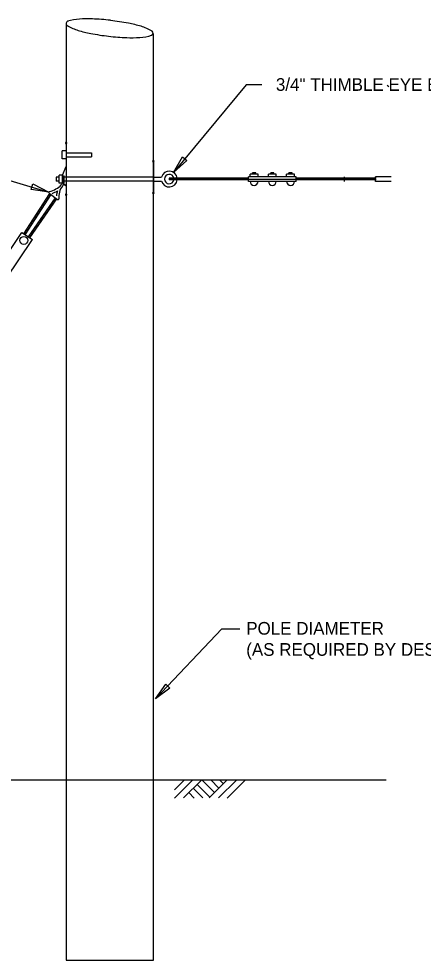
# Model space of a CAD drawing. Extents: x 1299104.8 to 1299141.6, y 239639.8 to 239661.8.
# Drawn here: x 1299120.32 to 1299124.15, y 239645.41 to 239654.32 of the extents above; entities that cross this region are included whole.
import ezdxf

# ---------------------------------------------------------------- set-up
doc = ezdxf.new("R2010")
doc.units = 0
doc.layers.add('DIM TXT', color=7, linetype='Continuous')

msp = doc.modelspace()

# ---------------------------------------------------------------- linework, layer by layer
at = {"layer": 'DIM TXT'}
for p, q in [((1299120.77, 239654.2729), (1299120.77, 239647.1125)), ((1299121.595, 239647.1125), (1299121.595, 239654.1755)), ((1299122.4738, 239653.6946), (1299121.786, 239652.8652)), ((1299122.6208, 239653.6946), (1299122.4738, 239653.6946)), ((1299123.8057, 239653.6923), (1299123.8207, 239653.6773)), ((1299120.7625, 239653.0683), (1299120.7325, 239653.0683)), ((1299120.7325, 239652.9933), (1299120.7325, 239653.0683)), ((1299120.77, 239653.0495), (1299121.01, 239653.0495)), ((1299121.01, 239653.0495), (1299121.01, 239653.012)), ((1299119.5594, 239652.9893), (1299120.6069, 239652.68)), ((1299120.7625, 239652.9933), (1299120.7325, 239652.9933)), ((1299120.77, 239653.012), (1299121.01, 239653.012)), ((1299120.7344, 239652.8386), (1299120.77, 239652.9214)), ((1299122.5325, 239652.8474), (1299122.5325, 239652.8624)), ((1299122.5625, 239652.8624), (1299122.5325, 239652.8624)), ((1299122.5625, 239652.8474), (1299122.5625, 239652.8624)), ((1299122.705, 239652.8474), (1299122.705, 239652.8624)), ((1299122.735, 239652.8624), (1299122.705, 239652.8624)), ((1299122.735, 239652.8474), (1299122.735, 239652.8624)), ((1299122.8775, 239652.8474), (1299122.8775, 239652.8624)), ((1299122.9075, 239652.8624), (1299122.8775, 239652.8624)), ((1299122.9075, 239652.8474), (1299122.9075, 239652.8624)), ((1299120.6771, 239652.8211), (1299120.6771, 239652.7836)), ((1299120.7044, 239652.8211), (1299120.6771, 239652.8211)), ((1299120.7044, 239652.7836), (1299120.6771, 239652.7836)), ((1299120.7044, 239652.7636), (1299120.7044, 239652.8386)), ((1299120.7344, 239652.8386), (1299120.7044, 239652.8386)), ((1299120.7344, 239652.7636), (1299120.7044, 239652.7636)), ((1299120.7344, 239652.7636), (1299120.7344, 239652.8386)), ((1299121.595, 239652.8211), (1299120.7344, 239652.8211)), ((1299121.595, 239652.7836), (1299120.7344, 239652.7836)), ((1299120.7387, 239652.7821), (1299120.7387, 239652.8326)), ((1299120.7387, 239652.8326), (1299120.7524, 239652.8326)), ((1299120.7524, 239652.7813), (1299120.7524, 239652.8326)), ((1299121.595, 239652.8211), (1299121.6724, 239652.8211)), ((1299121.595, 239652.7836), (1299121.6724, 239652.7836)), ((1299122.495, 239652.8099), (1299121.745, 239652.8099)), ((1299121.745, 239652.8099), (1299121.745, 239652.7949)), ((1299121.745, 239652.8099), (1299121.76, 239652.7949)), ((1299122.495, 239652.7949), (1299121.745, 239652.7949)), ((1299121.76, 239652.8099), (1299121.775, 239652.7949)), ((1299121.775, 239652.8099), (1299121.79, 239652.7949)), ((1299121.79, 239652.8099), (1299121.805, 239652.7949)), ((1299121.805, 239652.8099), (1299121.82, 239652.7949)), ((1299121.82, 239652.8099), (1299121.835, 239652.7949)), ((1299121.835, 239652.8099), (1299121.85, 239652.7949)), ((1299121.85, 239652.8099), (1299121.865, 239652.7949)), ((1299121.865, 239652.8099), (1299121.88, 239652.7949)), ((1299121.88, 239652.8099), (1299121.895, 239652.7949)), ((1299121.895, 239652.8099), (1299121.91, 239652.7949)), ((1299121.91, 239652.8099), (1299121.925, 239652.7949)), ((1299121.925, 239652.8099), (1299121.94, 239652.7949)), ((1299121.94, 239652.8099), (1299121.955, 239652.7949)), ((1299121.955, 239652.8099), (1299121.97, 239652.7949)), ((1299121.97, 239652.8099), (1299121.985, 239652.7949)), ((1299121.985, 239652.8099), (1299122, 239652.7949)), ((1299122, 239652.8099), (1299122.015, 239652.7949)), ((1299122.015, 239652.8099), (1299122.03, 239652.7949)), ((1299122.03, 239652.8099), (1299122.045, 239652.7949)), ((1299122.045, 239652.8099), (1299122.06, 239652.7949)), ((1299122.06, 239652.8099), (1299122.075, 239652.7949)), ((1299122.075, 239652.8099), (1299122.09, 239652.7949)), ((1299122.09, 239652.8099), (1299122.105, 239652.7949)), ((1299122.105, 239652.8099), (1299122.12, 239652.7949)), ((1299122.12, 239652.8099), (1299122.135, 239652.7949)), ((1299122.135, 239652.8099), (1299122.15, 239652.7949)), ((1299122.15, 239652.8099), (1299122.165, 239652.7949)), ((1299122.165, 239652.8099), (1299122.18, 239652.7949)), ((1299122.18, 239652.8099), (1299122.195, 239652.7949)), ((1299122.195, 239652.8099), (1299122.21, 239652.7949)), ((1299122.21, 239652.8099), (1299122.225, 239652.7949)), ((1299122.225, 239652.8099), (1299122.24, 239652.7949)), ((1299122.24, 239652.8099), (1299122.255, 239652.7949)), ((1299122.255, 239652.8099), (1299122.27, 239652.7949)), ((1299122.27, 239652.8099), (1299122.285, 239652.7949)), ((1299122.285, 239652.8099), (1299122.3, 239652.7949)), ((1299122.3, 239652.8099), (1299122.315, 239652.7949)), ((1299122.315, 239652.8099), (1299122.33, 239652.7949)), ((1299122.33, 239652.8099), (1299122.345, 239652.7949)), ((1299122.345, 239652.8099), (1299122.36, 239652.7949)), ((1299122.36, 239652.8099), (1299122.375, 239652.7949)), ((1299122.375, 239652.8099), (1299122.39, 239652.7949)), ((1299122.39, 239652.8099), (1299122.405, 239652.7949)), ((1299122.405, 239652.8099), (1299122.42, 239652.7949)), ((1299122.42, 239652.8099), (1299122.435, 239652.7949)), ((1299122.435, 239652.8099), (1299122.45, 239652.7949)), ((1299122.45, 239652.8099), (1299122.465, 239652.7949)), ((1299122.465, 239652.8099), (1299122.48, 239652.7949)), ((1299122.48, 239652.8099), (1299122.495, 239652.7949)), ((1299122.495, 239652.7799), (1299122.495, 239652.8249)), ((1299122.945, 239652.8249), (1299122.495, 239652.8249)), ((1299122.495, 239652.8024), (1299122.945, 239652.8024)), ((1299122.945, 239652.7799), (1299122.495, 239652.7799)), ((1299122.51, 239652.8249), (1299122.51, 239652.8474)), ((1299122.585, 239652.8474), (1299122.51, 239652.8474)), ((1299122.585, 239652.8249), (1299122.585, 239652.8474)), ((1299122.7575, 239652.8474), (1299122.6825, 239652.8474)), ((1299122.6825, 239652.8249), (1299122.6825, 239652.8474)), ((1299122.7575, 239652.8249), (1299122.7575, 239652.8474)), ((1299122.855, 239652.8249), (1299122.855, 239652.8474)), ((1299122.93, 239652.8474), (1299122.855, 239652.8474)), ((1299122.93, 239652.8249), (1299122.93, 239652.8474)), ((1299122.945, 239652.7799), (1299122.945, 239652.8249)), ((1299123.695, 239652.8099), (1299122.945, 239652.8099)), ((1299122.945, 239652.8099), (1299122.96, 239652.7949)), ((1299123.695, 239652.7949), (1299122.945, 239652.7949)), ((1299122.96, 239652.8099), (1299122.975, 239652.7949)), ((1299122.975, 239652.8099), (1299122.99, 239652.7949)), ((1299122.99, 239652.8099), (1299123.005, 239652.7949)), ((1299123.005, 239652.8099), (1299123.02, 239652.7949)), ((1299123.02, 239652.8099), (1299123.035, 239652.7949)), ((1299123.035, 239652.8099), (1299123.05, 239652.7949)), ((1299123.05, 239652.8099), (1299123.065, 239652.7949)), ((1299123.065, 239652.8099), (1299123.08, 239652.7949)), ((1299123.08, 239652.8099), (1299123.095, 239652.7949)), ((1299123.095, 239652.8099), (1299123.11, 239652.7949)), ((1299123.11, 239652.8099), (1299123.125, 239652.7949)), ((1299123.125, 239652.8099), (1299123.14, 239652.7949)), ((1299123.14, 239652.8099), (1299123.155, 239652.7949)), ((1299123.155, 239652.8099), (1299123.17, 239652.7949)), ((1299123.17, 239652.8099), (1299123.185, 239652.7949)), ((1299123.185, 239652.8099), (1299123.2, 239652.7949)), ((1299123.2, 239652.8099), (1299123.215, 239652.7949)), ((1299123.215, 239652.8099), (1299123.23, 239652.7949)), ((1299123.23, 239652.8099), (1299123.245, 239652.7949)), ((1299123.245, 239652.8099), (1299123.26, 239652.7949)), ((1299123.26, 239652.8099), (1299123.275, 239652.7949)), ((1299123.275, 239652.8099), (1299123.29, 239652.7949)), ((1299123.29, 239652.8099), (1299123.305, 239652.7949)), ((1299123.305, 239652.8099), (1299123.32, 239652.7949)), ((1299123.32, 239652.8099), (1299123.335, 239652.7949)), ((1299123.335, 239652.8099), (1299123.35, 239652.7949)), ((1299123.35, 239652.8099), (1299123.365, 239652.7949)), ((1299123.365, 239652.8099), (1299123.38, 239652.7949)), ((1299123.38, 239652.8099), (1299123.395, 239652.7949)), ((1299123.395, 239652.8099), (1299123.41, 239652.7949)), ((1299123.4036, 239652.7799), (1299123.4036, 239652.8249)), ((1299123.7036, 239652.8099), (1299123.4036, 239652.8099)), ((1299123.4036, 239652.8099), (1299123.4186, 239652.7949)), ((1299123.7036, 239652.7949), (1299123.4036, 239652.7949)), ((1299123.41, 239652.8099), (1299123.425, 239652.7949)), ((1299123.4186, 239652.8099), (1299123.4336, 239652.7949)), ((1299123.425, 239652.8099), (1299123.44, 239652.7949)), ((1299123.4336, 239652.8099), (1299123.4486, 239652.7949)), ((1299123.44, 239652.8099), (1299123.455, 239652.7949)), ((1299123.4486, 239652.8099), (1299123.4636, 239652.7949)), ((1299123.455, 239652.8099), (1299123.47, 239652.7949)), ((1299123.4636, 239652.8099), (1299123.4786, 239652.7949)), ((1299123.47, 239652.8099), (1299123.485, 239652.7949)), ((1299123.4786, 239652.8099), (1299123.4936, 239652.7949)), ((1299123.485, 239652.8099), (1299123.5, 239652.7949)), ((1299123.4936, 239652.8099), (1299123.5086, 239652.7949)), ((1299123.5, 239652.8099), (1299123.515, 239652.7949)), ((1299123.5086, 239652.8099), (1299123.5236, 239652.7949)), ((1299123.515, 239652.8099), (1299123.53, 239652.7949)), ((1299123.5236, 239652.8099), (1299123.5386, 239652.7949)), ((1299123.53, 239652.8099), (1299123.545, 239652.7949)), ((1299123.5386, 239652.8099), (1299123.5536, 239652.7949)), ((1299123.545, 239652.8099), (1299123.56, 239652.7949)), ((1299123.5536, 239652.8099), (1299123.5686, 239652.7949)), ((1299123.56, 239652.8099), (1299123.575, 239652.7949)), ((1299123.5686, 239652.8099), (1299123.5836, 239652.7949)), ((1299123.575, 239652.8099), (1299123.59, 239652.7949)), ((1299123.5836, 239652.8099), (1299123.5986, 239652.7949)), ((1299123.59, 239652.8099), (1299123.605, 239652.7949)), ((1299123.5986, 239652.8099), (1299123.6136, 239652.7949)), ((1299123.605, 239652.8099), (1299123.62, 239652.7949)), ((1299123.6136, 239652.8099), (1299123.6286, 239652.7949)), ((1299123.62, 239652.8099), (1299123.635, 239652.7949)), ((1299123.6286, 239652.8099), (1299123.6436, 239652.7949)), ((1299123.635, 239652.8099), (1299123.65, 239652.7949)), ((1299123.6436, 239652.8099), (1299123.6586, 239652.7949)), ((1299123.65, 239652.8099), (1299123.665, 239652.7949)), ((1299123.665, 239652.8099), (1299123.68, 239652.7949)), ((1299123.68, 239652.8099), (1299123.695, 239652.7949)), ((1299123.695, 239652.7799), (1299123.695, 239652.8249)), ((1299123.845, 239652.8249), (1299123.695, 239652.8249)), ((1299123.845, 239652.7799), (1299123.695, 239652.7799)), ((1299120.7471, 239652.7547), (1299120.77, 239652.7386)), ((1299120.3702, 239652.2839), (1299120.6164, 239652.6649)), ((1299120.3826, 239652.2756), (1299120.6283, 239652.6558)), ((1299120.413, 239652.2552), (1299120.6701, 239652.6242)), ((1299120.4254, 239652.2468), (1299120.6819, 239652.6149)), ((1299120.5866, 239652.5913), (1299120.5659, 239652.5868)), ((1299120.5948, 239652.6039), (1299120.574, 239652.5994)), ((1299120.6029, 239652.6165), (1299120.5822, 239652.612)), ((1299120.6111, 239652.6291), (1299120.5903, 239652.6246)), ((1299120.6192, 239652.6417), (1299120.5985, 239652.6372)), ((1299120.6273, 239652.6543), (1299120.6066, 239652.6498)), ((1299120.609, 239652.6705), (1299120.6891, 239652.6095)), ((1299120.6632, 239652.5881), (1299120.6424, 239652.5844)), ((1299120.6718, 239652.6004), (1299120.6509, 239652.5967)), ((1299120.6804, 239652.6127), (1299120.6595, 239652.609)), ((1299120.5296, 239652.5031), (1299120.5089, 239652.4986)), ((1299120.5378, 239652.5157), (1299120.5171, 239652.5112)), ((1299120.5459, 239652.5283), (1299120.5252, 239652.5238)), ((1299120.5541, 239652.5409), (1299120.5333, 239652.5364)), ((1299120.5622, 239652.5535), (1299120.5415, 239652.549)), ((1299120.5704, 239652.5661), (1299120.5496, 239652.5616)), ((1299120.5785, 239652.5787), (1299120.5578, 239652.5742)), ((1299120.6032, 239652.502), (1299120.5823, 239652.4982)), ((1299120.6118, 239652.5143), (1299120.5909, 239652.5105)), ((1299120.6204, 239652.5266), (1299120.5995, 239652.5228)), ((1299120.6289, 239652.5389), (1299120.608, 239652.5352)), ((1299120.6375, 239652.5512), (1299120.6166, 239652.5475)), ((1299120.6461, 239652.5635), (1299120.6252, 239652.5598)), ((1299120.6547, 239652.5758), (1299120.6338, 239652.5721)), ((1299120.4727, 239652.4149), (1299120.4519, 239652.4104)), ((1299120.4808, 239652.4275), (1299120.4601, 239652.423)), ((1299120.4889, 239652.4401), (1299120.4682, 239652.4356)), ((1299120.4971, 239652.4527), (1299120.4763, 239652.4482)), ((1299120.5052, 239652.4653), (1299120.4845, 239652.4608)), ((1299120.5134, 239652.4779), (1299120.4926, 239652.4734)), ((1299120.5215, 239652.4905), (1299120.5008, 239652.486)), ((1299120.5346, 239652.4035), (1299120.5137, 239652.3998)), ((1299120.5432, 239652.4158), (1299120.5223, 239652.4121)), ((1299120.5517, 239652.4281), (1299120.5309, 239652.4244)), ((1299120.5603, 239652.4404), (1299120.5394, 239652.4367)), ((1299120.5689, 239652.4527), (1299120.548, 239652.449)), ((1299120.5775, 239652.465), (1299120.5566, 239652.4613)), ((1299120.586, 239652.4773), (1299120.5652, 239652.4736)), ((1299120.5946, 239652.4897), (1299120.5737, 239652.4859)), ((1299120.4157, 239652.3267), (1299120.3949, 239652.3222)), ((1299120.4238, 239652.3393), (1299120.4031, 239652.3348)), ((1299120.432, 239652.3519), (1299120.4112, 239652.3474)), ((1299120.4401, 239652.3645), (1299120.4194, 239652.36)), ((1299120.4482, 239652.3771), (1299120.4275, 239652.3726)), ((1299120.4564, 239652.3897), (1299120.4356, 239652.3852)), ((1299120.4645, 239652.4023), (1299120.4438, 239652.3978)), ((1299120.4746, 239652.3174), (1299120.4537, 239652.3136)), ((1299120.4831, 239652.3297), (1299120.4623, 239652.3259)), ((1299120.4917, 239652.342), (1299120.4708, 239652.3382)), ((1299120.5003, 239652.3543), (1299120.4794, 239652.3506)), ((1299120.5089, 239652.3666), (1299120.488, 239652.3629)), ((1299120.5174, 239652.3789), (1299120.4966, 239652.3752)), ((1299120.526, 239652.3912), (1299120.5051, 239652.3875)), ((1299120.1004, 239651.923), (1299120.3512, 239652.2966)), ((1299120.2001, 239651.8561), (1299120.4509, 239652.2298)), ((1299120.3512, 239652.2966), (1299120.4509, 239652.2298)), ((1299120.3912, 239652.2889), (1299120.3705, 239652.2844)), ((1299120.3994, 239652.3015), (1299120.3786, 239652.297)), ((1299120.3831, 239652.2763), (1299120.3821, 239652.2761)), ((1299120.4075, 239652.3141), (1299120.3868, 239652.3096)), ((1299120.4317, 239652.2558), (1299120.4164, 239652.2531)), ((1299120.4403, 239652.2681), (1299120.4194, 239652.2644)), ((1299120.4488, 239652.2804), (1299120.428, 239652.2767)), ((1299120.4574, 239652.2928), (1299120.4365, 239652.289)), ((1299120.466, 239652.3051), (1299120.4451, 239652.3013)), ((1299122.2433, 239648.5466), (1299121.614, 239647.8852)), ((1299122.2433, 239648.5466), (1299122.4137, 239648.5466)), ((1299114.989, 239647.1184), (1299123.7976, 239647.1184)), ((1299120.77, 239647.1125), (1299120.77, 239645.4117)), ((1299121.595, 239645.4117), (1299121.595, 239647.1125)), ((1299121.7938, 239647.0246), (1299121.8882, 239647.1183)), ((1299121.7938, 239646.9441), (1299121.9693, 239647.1183)), ((1299121.8813, 239646.9477), (1299122.0531, 239647.1183)), ((1299122.0098, 239647.0754), (1299122.1291, 239646.9551)), ((1299122.054, 239647.1183), (1299122.1738, 239646.9977)), ((1299122.1216, 239646.9468), (1299122.2944, 239647.1183)), ((1299122.1372, 239647.1183), (1299122.2147, 239647.0402)), ((1299122.2098, 239646.9464), (1299122.383, 239647.1183)), ((1299122.2214, 239647.1183), (1299122.2576, 239647.0818)), ((1299122.2933, 239646.9461), (1299122.4668, 239647.1183)), ((1299121.9307, 239646.9967), (1299121.9823, 239646.9445)), ((1299121.9725, 239647.0383), (1299122.0631, 239646.947)), ((1299120.77, 239645.4117), (1299121.595, 239645.4117))]:
    msp.add_line(p, q, dxfattribs=at)
for points in [[(1299120.77, 239653.1433), (1299120.77, 239652.6558)], [(1299121.595, 239652.9711), (1299121.595, 239652.6711)], [(1299120.7344, 239652.8386), (1299120.77, 239652.9214)], [(1299120.7471, 239652.7547), (1299120.7471, 239652.7547), (1299120.7471, 239652.7547), (1299120.7471, 239652.7547), (1299120.7471, 239652.7547)], [(1299120.77, 239652.7386), (1299120.7471, 239652.7547)]]:
    msp.add_lwpolyline(points, dxfattribs=at)
for points in [[(1299121.8694, 239653.0122), (1299121.9118, 239652.9781), (1299121.786, 239652.8652)], [(1299120.4397, 239652.7047), (1299120.4562, 239652.7565), (1299120.6069, 239652.68)], [(1299121.712, 239648.0229), (1299121.7506, 239647.9846), (1299121.614, 239647.8852)]]:
    msp.add_lwpolyline(points, close=True, dxfattribs=at)
msp.add_circle((1299120.3699, 239652.2217), 0.0375, dxfattribs=at)
for centre, radius, start, end in [((1299120.7937, 239654.2742), 0.0238, 96.44805, 249.24322), ((1299120.9264, 239653.8286), 0.4887, 93.66612, 106.98781), ((1299120.9709, 239653.1339), 1.1847, 87.70627, 93.66612), ((1299120.9264, 239652.022), 2.2976, 83.42757, 87.70627), ((1299120.9264, 239652.0206), 2.2976, 79.14886, 83.42757), ((1299121.1359, 239653.1136), 1.1847, 73.18901, 79.14886), ((1299121.0244, 239654.6773), 0.4887, 240.4327, 253.18901), ((1299121.2257, 239655.3436), 1.1847, 253.18901, 259.14886), ((1299121.3372, 239653.7799), 0.4887, 59.86732, 73.18901), ((1299121.5715, 239654.1835), 0.0219, 353.42757, 59.86732), ((1299121.4352, 239656.4366), 2.2976, 259.14886, 263.42757), ((1299121.4352, 239656.4366), 2.2976, 263.42757, 267.70627), ((1299121.3906, 239655.3246), 1.1847, 267.70627, 273.66612), ((1299121.4352, 239654.6299), 0.4887, 273.66612, 286.98781), ((1299121.5715, 239654.1835), 0.0219, 286.98781, 353.42757), ((1299120.77, 239653.1433), 0.0075, 0, 180), ((1299120.77, 239653.1433), 0.0075, 180, 0), ((1299121.595, 239652.9711), 0.0075, 0, 180), ((1299121.595, 239652.9711), 0.0075, 180, 0), ((1299121.745, 239652.8024), 0.075, 5.73917, 165.52249), ((1299120.7076, 239652.7739), 0.0295, 325.18074, 348.4872), ((1299120.7047, 239652.7697), 0.045, 311.57137, 348.91039), ((1299120.6646, 239652.7862), 0.0742, 343.38012, 356.77642), ((1299120.6646, 239652.7862), 0.0879, 343.38012, 356.77642), ((1299121.745, 239652.8024), 0.075, 194.47751, 354.26083), ((1299121.745, 239652.8024), 0.045, 9.59407, 350.40593), ((1299122.5475, 239652.7799), 0.0375, 180, 0), ((1299122.72, 239652.7799), 0.0375, 180, 0), ((1299122.8925, 239652.7799), 0.0375, 180, 0), ((1299120.6135, 239652.6765), 0.0075, 86.0943, 232.73967), ((1299120.5402, 239652.9411), 0.2675, 286.02642, 313.58773), ((1299120.5402, 239652.9411), 0.2911, 289.5501, 300.33215), ((1299120.877, 239652.6317), 0.1985, 162.98374, 176.5336), ((1299120.877, 239652.6317), 0.1766, 143.76489, 184.84148), ((1299120.7047, 239652.7697), 0.03, 311.57137, 334.86882), ((1299121.595, 239652.6711), 0.0075, 0, 180), ((1299121.595, 239652.6711), 0.0075, 180, 0), ((1299120.6937, 239652.6155), 0.0075, 232.73967, 9.96119), ((1299120.77, 239652.6558), 0.0075, 0, 180), ((1299120.77, 239652.6558), 0.0075, 180, 0)]:
    msp.add_arc(centre, radius, start, end, dxfattribs=at)

# ---------------------------------------------------------------- texts
for s, p in [('3/4" THIMBLE EYE BOLT', (1299122.7536, 239653.6372)), ('POLE DIAMETER', (1299122.4733, 239648.4916)), ('(AS REQUIRED BY DESIGN)', (1299122.4733, 239648.2916))]:
    msp.add_text(s, height=0.12, dxfattribs=at).set_placement(p)

doc.saveas('drawing.dxf')
